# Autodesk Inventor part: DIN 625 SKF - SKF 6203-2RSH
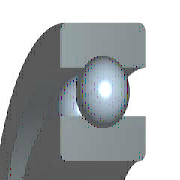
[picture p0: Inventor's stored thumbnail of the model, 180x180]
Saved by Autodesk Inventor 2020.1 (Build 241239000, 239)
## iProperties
Created: 2019-01
Part Number: DIN 625 SKF - SKF 6203-2RSH
Material: Stahl, weich
Description: Rillenkugellager, einreihig, beidseitig abgedichtet SKF
Document SubType Name: Modeling
Standard: DIN 625 SKF
Designer: lutzd
Standard Revision: SKF 2013
Standards Organization: DIN
Language: de-DE
Size Designation: SKF 6203-2RSH
Categories: <MemberInstance><Categories><Category DisplayName="Wellenteile" InternalName="7f7aeb1f-a693-4053-b835-cee3144e0d98" Mnemonic="SHFT"><Category DisplayName="Lager
Mass: 63.8278 g
Surface Area: 67.2137 cm^2
Volume: 8.13094 cm^3
Density: 7.85 g/cm^3
Appearance: Semi-Polished(8)
IsCustomPart: 0
Author: lutzd
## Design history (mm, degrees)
node "WorkPoint1"
revolve "Drehung1" stored, may be unused: angle "d6" = 360 deg
node "WorkAxis1"
node "WorkPlane3"
revolve "Drehung2" stored, may be unused: angle "d10" = 360 deg
node "WorkPlane4"
node "WorkPoint2"
sketch "Skizze5"
  geometry: L1 (14.25, 2.55)-(14.25, 9.45); L2 (16.32, 0)-(-16.32, 0) reference; L3 (14.25, 2.55)-(14.25, 9.45); A1 r 3.45 centre (14.25, 6) between (14.25, 2.55) and (14.25, 9.45); A2 r 3.45 centre (14.25, 6) between (16.32, 3.24) and (16.32, 8.76) reference
  constraints: 4 end point, 2 point on circle, 1 centre point, 1 concentric, 1 vertical
  dimensions: "d13" = 0 horizontal distance of A1.centre L1.start; "d15" = 6.9001 diameter of A1 (computed from msp_mdtd6)
revolve "Drehung3" sketch "Skizze5" stored, may be unused: angle "d16" = 360 deg
pattern_circular "Polare Anordnung1" dims "d17" = 65.95652 (= msp_pocet), angle "d19" = 360 deg
body "Solid1"
node "Skizze1"
node "Skizze4"
fillet "Rundung1" dims "d20" = 0.6 (= r)
sketch "Skizze2"
  geometry: L1 (8.5, 12)-(20, 12); L2 (8.5, 0)-(8.5, 12); L3 (20, 0)-(8.5, 0); L4 (20, 12)-(20, 0); L5 (0, 0)-(0, 20); L6 (0, 0)-(0, 20); L7 (-7.2, 0)-(43.2, 0) reference
  constraints: 12 end point, 3 vertical, 2 horizontal, 1 collinear, 1 other
  dimensions: "d1" = 17 diameter of L1.start L5 (= Diam); "d3" = 40 diameter of L1.end L5 (= DD); "d5" = 12 distance of L2.start L1.start (= msp_mdtd2)
sketch "Skizze3"
  geometry: L1 (16.32, 12)-(16.32, 8.76); L2 (12.18, 12)-(16.32, 12); L3 (12.18, 8.76)-(12.18, 12); L4 (12.18, 0)-(12.18, 3.24); L5 (16.32, 0)-(12.18, 0); L6 (16.32, 3.24)-(16.32, 0); L7 (20, 0)-(-20, 0) reference; L8 (20, 12)-(-20, 12) reference; L9 (0, -42.29)-(0, 61.29); L10 (0, 82.007)-(0, -63.007) reference; A1 r 3.45 centre (14.25, 6) between (16.32, 3.24) and (16.32, 8.76); A2 r 3.45 centre (14.25, 6) between (12.18, 8.76) and (12.18, 3.24)
  constraints: 14 end point, 4 collinear, 4 point on circle, 4 vertical, 2 centre point, 2 concentric, 2 horizontal, 2 point on line
  dimensions: "d9" = 6.9 diameter of A1 (= msp_mdtd6); "d21" = 12.18 distance between parallel lines of L9 L4 (= 0.5 x msp_d1); "d22" = 14.25 distance from line of L9 A1.centre (= 0.5 x msp_ds); "d23" = 16.32 distance between parallel lines of L9 L6 (= 0.5 x msp_dd1)
other parameters: "Diam" = 17 [user parameter; used in 3 equation terms], "DD" = 40 [user parameter; used in 3 equation terms], "B" = 12 [user parameter; used in 1 equation term], "r" = 0.6 [user parameter; used in 1 equation term], "msp_ds" = 28.5 (= 0.5 x Diam + 0.5 x DD) [user parameter; used in 5 equation terms], "msp_d0" = 6.9 (= -0.3 x Diam + 0.3 x DD) [user parameter; used in 4 equation terms], "msp_d1" = 24.36 (= msp_ds - 0.6 x msp_d0) [user parameter; used in 1 equation term], "msp_dd1" = 32.64 (= msp_ds + 0.6 x msp_d0) [user parameter; used in 1 equation term], "msp_pom" = 42.75 (= 1.5 x msp_ds) [user parameter; used in 1 equation term], "msp_mdtd2" = 12 (= B) [user parameter; used in 3 equation terms], "msp_mdtd4" = 28.5 (= msp_ds) [user parameter], "msp_mdtd6" = 6.9 (= msp_d0) [user parameter; used in 2 equation terms], "msp_mdtd7" = 6 (= 0.5 x msp_mdtd2) [user parameter], "msp_pocet" = 65.95652 (computed from msp_d0, msp_pom) [user parameter; used in 1 equation term], "d2" = 72 (derived), "d4" = 19 (derived), "d7" = 0, "d8" = 15.6 (derived), "d11" = -12 (computed from msp_mdtd2), "d12" = 0 (derived), "d14" = 15.6001 (derived), "d26" = 0, "d27" = 0, "d28" = 0, "d29" = 0, "d30" = 0
